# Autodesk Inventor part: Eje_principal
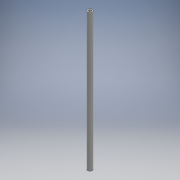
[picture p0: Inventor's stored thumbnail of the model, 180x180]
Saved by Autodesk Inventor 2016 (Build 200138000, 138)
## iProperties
Created: 2016-10
Part Number: Eje_principal
Material: Generic
Document SubType Name: Modeling
Designer: Ingenieria
Density: 1 g/cm^3
Appearance: Default
Mass: 15381.2 g
Surface Area: 15483.8 cm^2
Volume: 15381.2 cm^3
Author: Ingenieria
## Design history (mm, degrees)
sketch "Sketch1"
  geometry: C1 r 50.8 at (0, 0); C2 r 30.8 at (0, 0); 1 further point
  constraints: 2 centre point, 2 coincident
  dimensions: "d0" = 101.6 diameter of C1; "d1" = 61.6 diameter of C2
extrude "Extrusion1" new body sketch "Sketch1" stored distance "d2" = 3000; taper "d3" = 0 deg
body "Solid1"
